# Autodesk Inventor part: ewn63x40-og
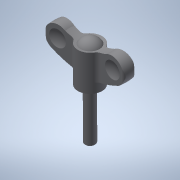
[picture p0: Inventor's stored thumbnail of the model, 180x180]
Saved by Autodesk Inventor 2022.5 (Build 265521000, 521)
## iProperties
Created: 2017-05
Part Number: ewn63x40-og
Material: 一般
Document SubType Name: Modeling
Designer: imaocorp
Density: 1 g/cm^3
Appearance: 既定
Author: imaocorp
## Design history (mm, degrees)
node "ewn63x40-og.x_t1"
node "ewn63x40-og"
node "Base1"
